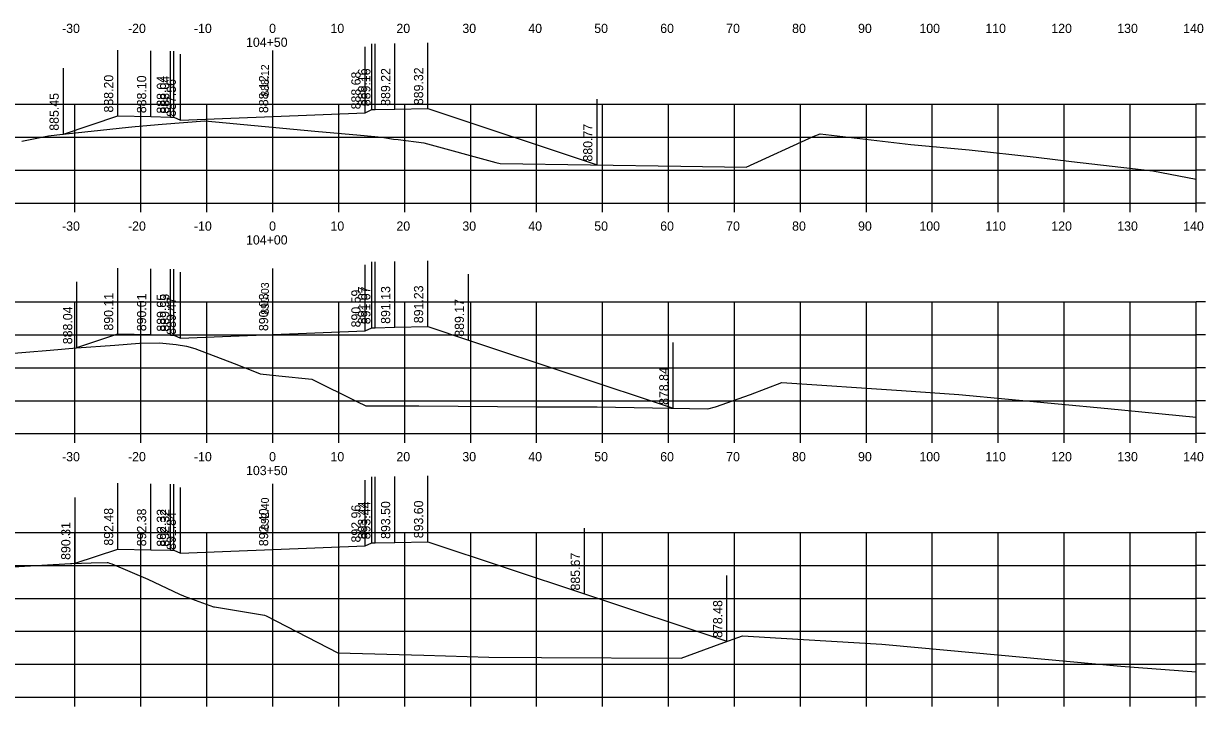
# Model space of a CAD drawing. Extents: x 1098669 to 1198896, y 698679 to 704410.
# Drawn here: x 1112271.4 to 1112450.6, y 701683.9 to 701787.5 of the extents above; entities that cross this region are included whole.
import ezdxf

# ---------------------------------------------------------------- set-up
doc = ezdxf.new("R2010")
doc.units = 0
for name, color, linetype in [('59', 7, 'Continuous'), ('Proposed Surface', 7, 'Continuous'), ('R_Axis', 7, 'Continuous'), ('R_Axis Annot', 7, 'Continuous'), ('R_Fin Surface', 7, 'Continuous'), ('R_Grid', 7, 'Continuous'), ('R_Xsect Elev', 7, 'Continuous')]:
    doc.layers.add(name, color=color, linetype=linetype)

msp = doc.modelspace()

# ---------------------------------------------------------------- linework, layer by layer
at = {"layer": 'Proposed Surface'}
for points in [[(1112271.11, 701769.66), (1112275.15, 701770.45), (1112276.45, 701770.61), (1112287.3, 701771.76), (1112288.3, 701771.87), (1112292.38, 701772.2), (1112298.89, 701772.74), (1112315.54, 701771.15), (1112322.47, 701770.54), (1112325.69, 701770.27), (1112327.49, 701769.96), (1112328.2, 701769.88), (1112332.09, 701769.4), (1112342.98, 701766.43), (1112343.64, 701766.25), (1112371.05, 701765.85), (1112380.95, 701765.71), (1112391.13, 701770.35), (1112392.16, 701770.77), (1112405.93, 701769.13), (1112414.75, 701768.33), (1112424.93, 701767.22), (1112430.3, 701766.55), (1112442.61, 701765.14), (1112449.18, 701763.89)], [(1112268.06, 701737.31), (1112275.43, 701737.92), (1112279.4, 701738.3), (1112285.22, 701738.7), (1112288.96, 701738.99), (1112291.99, 701739.02), (1112294.53, 701738.81), (1112296.09, 701738.52), (1112297.36, 701738.19), (1112303.33, 701735.89), (1112306.64, 701734.57), (1112307.25, 701734.34), (1112310.09, 701734.01), (1112315.11, 701733.53), (1112321.91, 701730.14), (1112323.3, 701729.49), (1112331.33, 701729.47), (1112349.21, 701729.33), (1112358.36, 701729.33), (1112375.13, 701729), (1112376.3, 701729.34), (1112381.63, 701731.21), (1112386.38, 701733.01), (1112404.51, 701731.79), (1112413.21, 701731.18), (1112435.81, 701729.07), (1112449.18, 701727.74)], [(1112269.82, 701705.06), (1112278.52, 701705.56), (1112278.72, 701705.57), (1112281.63, 701705.63), (1112284.08, 701705.68), (1112284.14, 701705.68), (1112284.44, 701705.6), (1112284.75, 701705.48), (1112290.25, 701703.15), (1112295.04, 701700.92), (1112295.66, 701700.63), (1112295.76, 701700.6), (1112300.21, 701698.97), (1112300.32, 701698.95), (1112307.93, 701697.72), (1112308.19, 701697.59), (1112319.06, 701691.99), (1112332.09, 701691.63), (1112341.92, 701691.31), (1112349.94, 701691.3), (1112371.11, 701691.17), (1112377.02, 701693.38), (1112380.41, 701694.57), (1112386.26, 701694.23), (1112401.5, 701693.32), (1112407.59, 701692.77), (1112437.76, 701689.99), (1112449.18, 701689.09)]]:
    msp.add_lwpolyline(points, dxfattribs=at)
at = {"layer": 'R_Axis'}
for p, q in [((1112449.18, 701760.26), (1112449.18, 701775.26)), ((1112450.58, 701775.26), (1112449.18, 701775.26)), ((1112450.58, 701770.26), (1112449.18, 701770.26)), ((1112450.58, 701765.26), (1112449.18, 701765.26)), ((1112169.18, 701760.26), (1112449.18, 701760.26)), ((1112279.18, 701758.86), (1112279.18, 701760.26)), ((1112289.18, 701758.86), (1112289.18, 701760.26)), ((1112299.18, 701758.86), (1112299.18, 701760.26)), ((1112309.18, 701758.86), (1112309.18, 701760.26)), ((1112319.18, 701758.86), (1112319.18, 701760.26)), ((1112329.18, 701758.86), (1112329.18, 701760.26)), ((1112339.18, 701758.86), (1112339.18, 701760.26)), ((1112349.18, 701758.86), (1112349.18, 701760.26)), ((1112359.18, 701758.86), (1112359.18, 701760.26)), ((1112369.18, 701758.86), (1112369.18, 701760.26)), ((1112379.18, 701758.86), (1112379.18, 701760.26)), ((1112389.18, 701758.86), (1112389.18, 701760.26)), ((1112399.18, 701758.86), (1112399.18, 701760.26)), ((1112409.18, 701758.86), (1112409.18, 701760.26)), ((1112419.18, 701758.86), (1112419.18, 701760.26)), ((1112429.18, 701758.86), (1112429.18, 701760.26)), ((1112439.18, 701758.86), (1112439.18, 701760.26)), ((1112449.18, 701758.86), (1112449.18, 701760.26)), ((1112450.58, 701760.26), (1112449.18, 701760.26)), ((1112449.18, 701725.26), (1112449.18, 701745.26)), ((1112450.58, 701745.26), (1112449.18, 701745.26)), ((1112450.58, 701740.26), (1112449.18, 701740.26)), ((1112450.58, 701735.26), (1112449.18, 701735.26)), ((1112450.58, 701730.26), (1112449.18, 701730.26)), ((1112169.18, 701725.26), (1112449.18, 701725.26)), ((1112279.18, 701723.86), (1112279.18, 701725.26)), ((1112289.18, 701723.86), (1112289.18, 701725.26)), ((1112299.18, 701723.86), (1112299.18, 701725.26)), ((1112309.18, 701723.86), (1112309.18, 701725.26)), ((1112319.18, 701723.86), (1112319.18, 701725.26)), ((1112329.18, 701723.86), (1112329.18, 701725.26)), ((1112339.18, 701723.86), (1112339.18, 701725.26)), ((1112349.18, 701723.86), (1112349.18, 701725.26)), ((1112359.18, 701723.86), (1112359.18, 701725.26)), ((1112369.18, 701723.86), (1112369.18, 701725.26)), ((1112379.18, 701723.86), (1112379.18, 701725.26)), ((1112389.18, 701723.86), (1112389.18, 701725.26)), ((1112399.18, 701723.86), (1112399.18, 701725.26)), ((1112409.18, 701723.86), (1112409.18, 701725.26)), ((1112419.18, 701723.86), (1112419.18, 701725.26)), ((1112429.18, 701723.86), (1112429.18, 701725.26)), ((1112439.18, 701723.86), (1112439.18, 701725.26)), ((1112449.18, 701723.86), (1112449.18, 701725.26)), ((1112450.58, 701725.26), (1112449.18, 701725.26)), ((1112449.18, 701685.26), (1112449.18, 701710.26)), ((1112450.58, 701710.26), (1112449.18, 701710.26)), ((1112450.58, 701705.26), (1112449.18, 701705.26)), ((1112450.58, 701700.26), (1112449.18, 701700.26)), ((1112450.58, 701695.26), (1112449.18, 701695.26)), ((1112450.58, 701690.26), (1112449.18, 701690.26)), ((1112169.18, 701685.26), (1112449.18, 701685.26)), ((1112279.18, 701683.86), (1112279.18, 701685.26)), ((1112289.18, 701683.86), (1112289.18, 701685.26)), ((1112299.18, 701683.86), (1112299.18, 701685.26)), ((1112309.18, 701683.86), (1112309.18, 701685.26)), ((1112319.18, 701683.86), (1112319.18, 701685.26)), ((1112329.18, 701683.86), (1112329.18, 701685.26)), ((1112339.18, 701683.86), (1112339.18, 701685.26)), ((1112349.18, 701683.86), (1112349.18, 701685.26)), ((1112359.18, 701683.86), (1112359.18, 701685.26)), ((1112369.18, 701683.86), (1112369.18, 701685.26)), ((1112379.18, 701683.86), (1112379.18, 701685.26)), ((1112389.18, 701683.86), (1112389.18, 701685.26)), ((1112399.18, 701683.86), (1112399.18, 701685.26)), ((1112409.18, 701683.86), (1112409.18, 701685.26)), ((1112419.18, 701683.86), (1112419.18, 701685.26)), ((1112429.18, 701683.86), (1112429.18, 701685.26)), ((1112439.18, 701683.86), (1112439.18, 701685.26)), ((1112449.18, 701683.86), (1112449.18, 701685.26)), ((1112450.58, 701685.26), (1112449.18, 701685.26))]:
    msp.add_line(p, q, dxfattribs=at)
at = {"layer": 'R_Fin Surface'}
for points in [[(1112277.42, 701770.71), (1112285.68, 701773.47), (1112290.68, 701773.37), (1112293.68, 701773.31), (1112294.18, 701773.31), (1112295.18, 701772.83), (1112309.18, 701773.39), (1112323.18, 701773.95), (1112324.18, 701774.43), (1112324.68, 701774.43), (1112327.68, 701774.49), (1112332.68, 701774.59), (1112358.34, 701766.03)], [(1112279.47, 701738.31), (1112285.68, 701740.38), (1112290.68, 701740.28), (1112293.68, 701740.22), (1112294.18, 701740.22), (1112295.18, 701739.74), (1112309.18, 701740.3), (1112323.18, 701740.86), (1112324.18, 701741.34), (1112324.68, 701741.34), (1112327.68, 701741.4), (1112332.68, 701741.5), (1112338.87, 701739.44), (1112369.87, 701729.1)], [(1112279.19, 701705.58), (1112285.68, 701707.74), (1112290.68, 701707.64), (1112293.68, 701707.58), (1112294.18, 701707.58), (1112295.18, 701707.1), (1112309.18, 701707.66), (1112323.18, 701708.22), (1112324.18, 701708.7), (1112324.68, 701708.7), (1112327.68, 701708.76), (1112332.68, 701708.86), (1112356.46, 701700.93), (1112378.04, 701693.74)]]:
    msp.add_lwpolyline(points, dxfattribs=at)
at = {"layer": 'R_Grid'}
for p, q in [((1112169.18, 701775.26), (1112449.18, 701775.26)), ((1112279.18, 701760.26), (1112279.18, 701775.26)), ((1112289.18, 701760.26), (1112289.18, 701775.26)), ((1112299.18, 701760.26), (1112299.18, 701775.26)), ((1112309.18, 701760.26), (1112309.18, 701775.26)), ((1112319.18, 701760.26), (1112319.18, 701775.26)), ((1112329.18, 701760.26), (1112329.18, 701775.26)), ((1112339.18, 701760.26), (1112339.18, 701775.26)), ((1112349.18, 701760.26), (1112349.18, 701775.26)), ((1112359.18, 701760.26), (1112359.18, 701775.26)), ((1112369.18, 701760.26), (1112369.18, 701775.26)), ((1112379.18, 701760.26), (1112379.18, 701775.26)), ((1112389.18, 701760.26), (1112389.18, 701775.26)), ((1112399.18, 701760.26), (1112399.18, 701775.26)), ((1112409.18, 701760.26), (1112409.18, 701775.26)), ((1112419.18, 701760.26), (1112419.18, 701775.26)), ((1112429.18, 701760.26), (1112429.18, 701775.26)), ((1112439.18, 701760.26), (1112439.18, 701775.26)), ((1112449.18, 701760.26), (1112449.18, 701775.26)), ((1112169.18, 701770.26), (1112449.18, 701770.26)), ((1112169.18, 701765.26), (1112449.18, 701765.26)), ((1112169.18, 701760.26), (1112449.18, 701760.26)), ((1112169.18, 701745.26), (1112449.18, 701745.26)), ((1112279.18, 701725.26), (1112279.18, 701745.26)), ((1112289.18, 701725.26), (1112289.18, 701745.26)), ((1112299.18, 701725.26), (1112299.18, 701745.26)), ((1112309.18, 701725.26), (1112309.18, 701745.26)), ((1112319.18, 701725.26), (1112319.18, 701745.26)), ((1112329.18, 701725.26), (1112329.18, 701745.26)), ((1112339.18, 701725.26), (1112339.18, 701745.26)), ((1112349.18, 701725.26), (1112349.18, 701745.26)), ((1112359.18, 701725.26), (1112359.18, 701745.26)), ((1112369.18, 701725.26), (1112369.18, 701745.26)), ((1112379.18, 701725.26), (1112379.18, 701745.26)), ((1112389.18, 701725.26), (1112389.18, 701745.26)), ((1112399.18, 701725.26), (1112399.18, 701745.26)), ((1112409.18, 701725.26), (1112409.18, 701745.26)), ((1112419.18, 701725.26), (1112419.18, 701745.26)), ((1112429.18, 701725.26), (1112429.18, 701745.26)), ((1112439.18, 701725.26), (1112439.18, 701745.26)), ((1112449.18, 701725.26), (1112449.18, 701745.26)), ((1112169.18, 701740.26), (1112449.18, 701740.26)), ((1112169.18, 701735.26), (1112449.18, 701735.26)), ((1112169.18, 701730.26), (1112449.18, 701730.26)), ((1112169.18, 701725.26), (1112449.18, 701725.26)), ((1112169.18, 701710.26), (1112449.18, 701710.26)), ((1112279.18, 701685.26), (1112279.18, 701710.26)), ((1112289.18, 701685.26), (1112289.18, 701710.26)), ((1112299.18, 701685.26), (1112299.18, 701710.26)), ((1112309.18, 701685.26), (1112309.18, 701710.26)), ((1112319.18, 701685.26), (1112319.18, 701710.26)), ((1112329.18, 701685.26), (1112329.18, 701710.26)), ((1112339.18, 701685.26), (1112339.18, 701710.26)), ((1112349.18, 701685.26), (1112349.18, 701710.26)), ((1112359.18, 701685.26), (1112359.18, 701710.26)), ((1112369.18, 701685.26), (1112369.18, 701710.26)), ((1112379.18, 701685.26), (1112379.18, 701710.26)), ((1112389.18, 701685.26), (1112389.18, 701710.26)), ((1112399.18, 701685.26), (1112399.18, 701710.26)), ((1112409.18, 701685.26), (1112409.18, 701710.26)), ((1112419.18, 701685.26), (1112419.18, 701710.26)), ((1112429.18, 701685.26), (1112429.18, 701710.26)), ((1112439.18, 701685.26), (1112439.18, 701710.26)), ((1112449.18, 701685.26), (1112449.18, 701710.26)), ((1112169.18, 701705.26), (1112449.18, 701705.26)), ((1112169.18, 701700.26), (1112449.18, 701700.26)), ((1112169.18, 701695.26), (1112449.18, 701695.26)), ((1112169.18, 701690.26), (1112449.18, 701690.26)), ((1112169.18, 701685.26), (1112449.18, 701685.26))]:
    msp.add_line(p, q, dxfattribs=at)
at = {"layer": 'R_Xsect Elev'}
for p, q in [((1112324.18, 701774.43), (1112324.18, 701784.43)), ((1112324.68, 701774.43), (1112324.68, 701784.43)), ((1112327.68, 701774.49), (1112327.68, 701784.49)), ((1112332.68, 701774.59), (1112332.68, 701784.59)), ((1112285.68, 701773.47), (1112285.68, 701783.47)), ((1112290.68, 701773.37), (1112290.68, 701783.37)), ((1112293.68, 701773.31), (1112293.68, 701783.31)), ((1112294.18, 701773.31), (1112294.18, 701783.31)), ((1112295.18, 701772.83), (1112295.18, 701782.83)), ((1112309.18, 701773.39), (1112309.18, 701783.39)), ((1112309.18, 701773.39), (1112309.18, 701783.39)), ((1112323.18, 701773.95), (1112323.18, 701783.95)), ((1112277.42, 701770.71), (1112277.42, 701780.71)), ((1112358.34, 701766.03), (1112358.34, 701776.03)), ((1112285.68, 701740.38), (1112285.68, 701750.38)), ((1112290.68, 701740.28), (1112290.68, 701750.28)), ((1112293.68, 701740.22), (1112293.68, 701750.22)), ((1112294.18, 701740.22), (1112294.18, 701750.22)), ((1112309.18, 701740.3), (1112309.18, 701750.3)), ((1112309.18, 701740.3), (1112309.18, 701750.3)), ((1112323.18, 701740.86), (1112323.18, 701750.86)), ((1112324.18, 701741.34), (1112324.18, 701751.34)), ((1112324.68, 701741.34), (1112324.68, 701751.34)), ((1112327.68, 701741.4), (1112327.68, 701751.4)), ((1112332.68, 701741.5), (1112332.68, 701751.5)), ((1112279.47, 701738.31), (1112279.47, 701748.31)), ((1112295.18, 701739.74), (1112295.18, 701749.74)), ((1112338.87, 701739.44), (1112338.87, 701749.44)), ((1112369.87, 701729.1), (1112369.87, 701739.1)), ((1112285.68, 701707.74), (1112285.68, 701717.74)), ((1112323.18, 701708.22), (1112323.18, 701718.22)), ((1112324.18, 701708.7), (1112324.18, 701718.7)), ((1112324.68, 701708.7), (1112324.68, 701718.7)), ((1112327.68, 701708.76), (1112327.68, 701718.76)), ((1112332.68, 701708.86), (1112332.68, 701718.86)), ((1112290.68, 701707.64), (1112290.68, 701717.64)), ((1112293.68, 701707.58), (1112293.68, 701717.58)), ((1112294.18, 701707.58), (1112294.18, 701717.58)), ((1112295.18, 701707.1), (1112295.18, 701717.1)), ((1112309.18, 701707.66), (1112309.18, 701717.66)), ((1112309.18, 701707.66), (1112309.18, 701717.66)), ((1112279.19, 701705.58), (1112279.19, 701715.58)), ((1112356.46, 701700.93), (1112356.46, 701710.93)), ((1112378.04, 701693.74), (1112378.04, 701703.74))]:
    msp.add_line(p, q, dxfattribs=at)

# ---------------------------------------------------------------- texts
at = {"layer": '59'}
for s, p in [(' 889.16', (1112323.48, 701774.43)), (' 889.16', (1112323.98, 701774.43)), (' 889.22', (1112326.98, 701774.49)), (' 889.32', (1112331.98, 701774.59)), (' 888.20', (1112284.98, 701773.47)), (' 888.10', (1112289.98, 701773.37)), (' 888.04', (1112292.98, 701773.31)), (' 888.04', (1112293.48, 701773.31)), (' 887.56', (1112294.48, 701772.83)), (' 888.12', (1112308.48, 701773.39)), (' 888.68', (1112322.48, 701773.95)), (' 885.45', (1112276.72, 701770.71)), (' 880.77', (1112357.64, 701766.03)), (' 890.11', (1112284.98, 701740.38)), (' 890.01', (1112289.98, 701740.28)), (' 889.95', (1112292.98, 701740.22)), (' 889.95', (1112293.48, 701740.22)), (' 890.03', (1112308.48, 701740.3)), (' 890.59', (1112322.48, 701740.86)), (' 891.07', (1112323.48, 701741.34)), (' 891.07', (1112323.98, 701741.34)), (' 891.13', (1112326.98, 701741.4)), (' 891.23', (1112331.98, 701741.5)), (' 889.47', (1112294.48, 701739.74)), (' 889.17', (1112338.17, 701739.44)), (' 888.04', (1112278.77, 701738.31)), (' 878.84', (1112369.17, 701729.1)), (' 892.96', (1112322.48, 701708.22)), (' 893.44', (1112323.48, 701708.7)), (' 893.44', (1112323.98, 701708.7)), (' 893.50', (1112326.98, 701708.76)), (' 893.60', (1112331.98, 701708.86)), (' 892.48', (1112284.98, 701707.74)), (' 892.38', (1112289.98, 701707.64)), (' 892.32', (1112292.98, 701707.58)), (' 892.32', (1112293.48, 701707.58)), (' 891.84', (1112294.48, 701707.1)), (' 892.40', (1112308.48, 701707.66)), (' 890.31', (1112278.49, 701705.58)), (' 885.67', (1112355.76, 701700.93)), (' 878.48', (1112377.34, 701693.74))]:
    msp.add_text(s, height=1.4, rotation=90, dxfattribs=at).set_placement(p)
at = {"layer": 'R_Axis Annot'}
for s, p in [('-30', (1112277.22, 701786.06)), ('-20', (1112287.22, 701786.06)), ('-10', (1112297.22, 701786.06)), ('0', (1112308.62, 701786.06)), ('10', (1112317.92, 701786.06)), ('20', (1112327.92, 701786.06)), ('30', (1112337.92, 701786.06)), ('40', (1112347.92, 701786.06)), ('50', (1112357.92, 701786.06)), ('60', (1112367.92, 701786.06)), ('70', (1112377.92, 701786.06)), ('80', (1112387.92, 701786.06)), ('90', (1112397.92, 701786.06)), ('100', (1112407.22, 701786.06)), ('110', (1112417.22, 701786.06)), ('120', (1112427.22, 701786.06)), ('130', (1112437.22, 701786.06)), ('140', (1112447.22, 701786.06)), ('104+50', (1112305.12, 701783.96)), ('-30', (1112277.22, 701756.06)), ('-20', (1112287.22, 701756.06)), ('-10', (1112297.22, 701756.06)), ('0', (1112308.62, 701756.06)), ('10', (1112317.92, 701756.06)), ('20', (1112327.92, 701756.06)), ('30', (1112337.92, 701756.06)), ('40', (1112347.92, 701756.06)), ('50', (1112357.92, 701756.06)), ('60', (1112367.92, 701756.06)), ('70', (1112377.92, 701756.06)), ('80', (1112387.92, 701756.06)), ('90', (1112397.92, 701756.06)), ('100', (1112407.22, 701756.06)), ('110', (1112417.22, 701756.06)), ('120', (1112427.22, 701756.06)), ('130', (1112437.22, 701756.06)), ('140', (1112447.22, 701756.06)), ('104+00', (1112305.12, 701753.96)), ('-30', (1112277.22, 701721.06)), ('-20', (1112287.22, 701721.06)), ('-10', (1112297.22, 701721.06)), ('0', (1112308.62, 701721.06)), ('10', (1112317.92, 701721.06)), ('20', (1112327.92, 701721.06)), ('30', (1112337.92, 701721.06)), ('40', (1112347.92, 701721.06)), ('50', (1112357.92, 701721.06)), ('60', (1112367.92, 701721.06)), ('70', (1112377.92, 701721.06)), ('80', (1112387.92, 701721.06)), ('90', (1112397.92, 701721.06)), ('100', (1112407.22, 701721.06)), ('110', (1112417.22, 701721.06)), ('120', (1112427.22, 701721.06)), ('130', (1112437.22, 701721.06)), ('140', (1112447.22, 701721.06)), ('103+50', (1112305.12, 701718.96))]:
    msp.add_text(s, height=1.4, dxfattribs=at).set_placement(p)
at = {"layer": 'R_Xsect Elev'}
for s, p in [('888.12', (1112308.58, 701776.39)), ('890.03', (1112308.58, 701743.3)), ('892.40', (1112308.58, 701710.66))]:
    msp.add_text(s, height=1.2, rotation=90, dxfattribs=at).set_placement(p)

doc.saveas('drawing.dxf')
